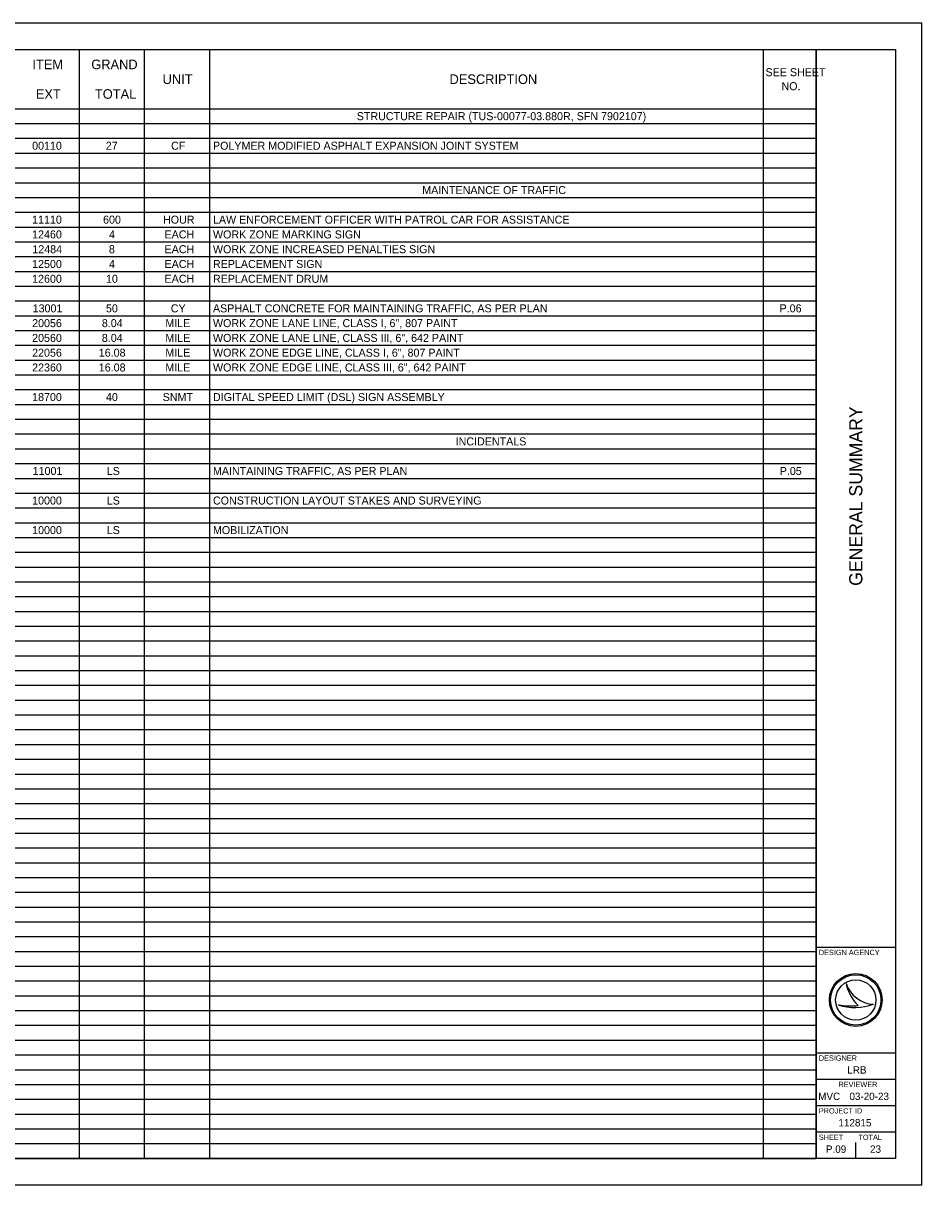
# Model space of a CAD drawing. Extents: x 0 to 924, y -62 to 22.
# Drawn here: x 16.98 to 34, y 0 to 22 of the extents above; entities that cross this region are included whole.
import ezdxf

# ---------------------------------------------------------------- set-up
doc = ezdxf.new("R2010")
doc.units = 0
for name, color, linetype in [('SH_Border', 7, 'Continuous'), ('SH_Cut_Line', 7, 'Continuous'), ('SH_Data', 7, 'Continuous'), ('SH_Text', 7, 'Continuous')]:
    doc.layers.add(name, color=color, linetype=linetype)

msp = doc.modelspace()

# ---------------------------------------------------------------- linework, layer by layer
at = {"layer": 'SH_Border'}
for p, q in [((32, 0.5), (32, 21.5)), ((32, 4.5), (33.5, 4.5)), ((32, 2.5), (33.5, 2.5)), ((32, 2), (33.5, 2)), ((32, 1.5), (33.5, 1.5)), ((32, 1), (33.5, 1))]:
    msp.add_line(p, q, dxfattribs=at)
msp.add_lwpolyline([(1.5, 21.5), (33.5, 21.5), (33.5, 0.5), (1.5, 0.5)], close=True, dxfattribs=at)
at = {"layer": 'SH_Cut_Line'}
msp.add_lwpolyline([(0, 0), (34, 0), (34, 22), (0, 22)], close=True, dxfattribs=at)
at = {"layer": 'SH_Data'}
for p, q in [((32.567, 3.81), (32.567, 3.81)), ((32.417, 3.41), (32.417, 3.41)), ((32.75, 3.5), (32.75, 3.5)), ((33.087, 3.419), (33.087, 3.419)), ((32.375, 0.675), (32.375, 0.675)), ((32.75, 0.5), (32.75, 0.8))]:
    msp.add_line(p, q, dxfattribs=at)
for radius in [0.5, 0.477, 0.477, 0.382]:
    msp.add_circle((32.75, 3.5), radius, dxfattribs=at)
for centre, radius, start, end in [((33.116, 3.998), 0.58, 198.9257, 198.9319), ((33.347, 3.97), 0.796, 191.6379, 191.6421), ((33.116, 3.998), 0.58, 198.9319, 267.1657), ((33.347, 3.97), 0.796, 191.6421, 226.0947), ((32.739, 4.37), 1.013, 251.4576, 290.0832), ((32.648, 4.654), 1.266, 259.4964, 259.4995), ((32.739, 4.37), 1.013, 251.4527, 251.4576), ((32.648, 4.654), 1.266, 259.4995, 276.6672)]:
    msp.add_arc(centre, radius, start, end, dxfattribs=at)
at = {"layer": 'SH_Text'}
for p, q in [((1.5, 21.5), (32, 21.5)), ((18.035, 21.5), (18.035, 0.5)), ((19.27, 21.5), (19.27, 0.5)), ((20.505, 21.5), (20.505, 0.5)), ((30.995, 21.5), (30.995, 0.5)), ((32, 21.5), (32, 0.5)), ((1.5, 20.38), (32, 20.38)), ((1.5, 20.1), (32, 20.1)), ((1.5, 19.82), (32, 19.82)), ((1.5, 19.54), (32, 19.54)), ((1.5, 19.26), (32, 19.26)), ((1.5, 18.98), (32, 18.98)), ((1.5, 18.7), (32, 18.7)), ((1.5, 18.42), (32, 18.42)), ((1.5, 18.14), (32, 18.14)), ((1.5, 17.86), (32, 17.86)), ((1.5, 17.58), (32, 17.58)), ((1.5, 17.3), (32, 17.3)), ((1.5, 17.02), (32, 17.02)), ((1.5, 16.74), (32, 16.74)), ((1.5, 16.46), (32, 16.46)), ((1.5, 16.18), (32, 16.18)), ((1.5, 15.9), (32, 15.9)), ((1.5, 15.62), (32, 15.62)), ((1.5, 15.34), (32, 15.34)), ((1.5, 15.06), (32, 15.06)), ((1.5, 14.78), (32, 14.78)), ((1.5, 14.5), (32, 14.5)), ((1.5, 14.22), (32, 14.22)), ((1.5, 13.94), (32, 13.94)), ((1.5, 13.66), (32, 13.66)), ((1.5, 13.38), (32, 13.38)), ((1.5, 13.1), (32, 13.1)), ((1.5, 12.82), (32, 12.82)), ((1.5, 12.54), (32, 12.54)), ((1.5, 12.26), (32, 12.26)), ((1.5, 11.98), (32, 11.98)), ((1.5, 11.7), (32, 11.7)), ((1.5, 11.42), (32, 11.42)), ((1.5, 11.14), (32, 11.14)), ((1.5, 10.86), (32, 10.86)), ((1.5, 10.58), (32, 10.58)), ((1.5, 10.3), (32, 10.3)), ((1.5, 10.02), (32, 10.02)), ((1.5, 9.74), (32, 9.74)), ((1.5, 9.46), (32, 9.46)), ((1.5, 9.18), (32, 9.18)), ((1.5, 8.9), (32, 8.9)), ((1.5, 8.62), (32, 8.62)), ((1.5, 8.34), (32, 8.34)), ((1.5, 8.06), (32, 8.06)), ((1.5, 7.78), (32, 7.78)), ((1.5, 7.5), (32, 7.5)), ((1.5, 7.22), (32, 7.22)), ((1.5, 6.94), (32, 6.94)), ((1.5, 6.66), (32, 6.66)), ((1.5, 6.38), (32, 6.38)), ((1.5, 6.1), (32, 6.1)), ((1.5, 5.82), (32, 5.82)), ((1.5, 5.54), (32, 5.54)), ((1.5, 5.26), (32, 5.26)), ((1.5, 4.98), (32, 4.98)), ((1.5, 4.7), (32, 4.7)), ((1.5, 4.42), (32, 4.42)), ((1.5, 4.14), (32, 4.14)), ((1.5, 3.86), (32, 3.86)), ((1.5, 3.58), (32, 3.58)), ((1.5, 3.3), (32, 3.3)), ((1.5, 3.02), (32, 3.02)), ((1.5, 2.74), (32, 2.74)), ((1.5, 2.46), (32, 2.46)), ((1.5, 2.18), (32, 2.18)), ((1.5, 1.9), (32, 1.9)), ((1.5, 1.62), (32, 1.62)), ((1.5, 1.34), (32, 1.34)), ((1.5, 1.06), (32, 1.06)), ((1.5, 0.78), (32, 0.78)), ((1.5, 0.5), (32, 0.5))]:
    msp.add_line(p, q, dxfattribs=at)

# ---------------------------------------------------------------- texts
at = {"layer": 'SH_Data'}
msp.add_text('GENERAL SUMMARY', height=0.25, rotation=90, dxfattribs=at).set_placement((32.875, 11.344))
for s, height, p in [('DESIGN AGENCY', 0.1, (32.05, 4.35)), ('DESIGNER', 0.1, (32.05, 2.35)), ('LRB', 0.14, (32.589, 2.105)), ('REVIEWER', 0.1, (32.422, 1.85)), ('MVC', 0.14, (32.038, 1.605)), ('03-20-23', 0.14, (32.629, 1.605)), ('PROJECT ID', 0.1, (32.05, 1.35)), ('112815', 0.14, (32.421, 1.105)), ('SHEET', 0.1, (32.05, 0.85)), ('TOTAL', 0.1, (32.8, 0.85)), ('P.09', 0.14, (32.184, 0.605)), ('23', 0.14, (33.02, 0.605))]:
    msp.add_text(s, height=height, dxfattribs=at).set_placement(p)
at = {"layer": 'SH_Text'}
for s, height, p in [('ITEM', 0.1818, (17.15, 21.129)), ('GRAND', 0.1818, (18.266, 21.129)), ('SEE SHEET ', 0.1515, (31.04, 20.997)), ('UNIT', 0.1818, (19.617, 20.849)), ('DESCRIPTION', 0.18184, (25.053, 20.849)), ('EXT', 0.1818, (17.215, 20.569)), ('TOTAL', 0.1818, (18.335, 20.569)), ('NO.', 0.1515, (31.342, 20.732)), ('STRUCTURE REPAIR (TUS-00077-03.880R, SFN 7902107)', 0.15153, (23.295, 20.164)), ('00110', 0.1515, (17.145, 19.604)), ('27', 0.1515, (18.54, 19.604)), ('CF', 0.1515, (19.778, 19.604)), ('POLYMER MODIFIED ASPHALT EXPANSION JOINT SYSTEM', 0.15153, (20.571, 19.604)), ('MAINTENANCE OF TRAFFIC', 0.15153, (24.536, 18.764)), ('11110', 0.1515, (17.145, 18.204)), ('600', 0.1515, (18.489, 18.204)), ('HOUR', 0.1515, (19.625, 18.204)), ('LAW ENFORCEMENT OFFICER WITH PATROL CAR FOR ASSISTANCE', 0.15153, (20.571, 18.204)), ('12460', 0.1515, (17.145, 17.924)), ('4', 0.152, (18.602, 17.924)), ('EACH', 0.1515, (19.654, 17.924)), ('WORK ZONE MARKING SIGN', 0.15153, (20.571, 17.924)), ('12484', 0.1515, (17.149, 17.644)), ('8', 0.152, (18.599, 17.644)), ('EACH', 0.1515, (19.654, 17.644)), ('WORK ZONE INCREASED PENALTIES SIGN', 0.15153, (20.571, 17.644)), ('12500', 0.1515, (17.145, 17.364)), ('4', 0.152, (18.602, 17.364)), ('EACH', 0.1515, (19.654, 17.364)), ('REPLACEMENT SIGN', 0.15153, (20.571, 17.364)), ('12600', 0.1515, (17.145, 17.084)), ('10', 0.1515, (18.544, 17.084)), ('EACH', 0.1515, (19.654, 17.084)), ('REPLACEMENT DRUM', 0.15153, (20.571, 17.084)), ('13001', 0.1515, (17.155, 16.524)), ('50', 0.1515, (18.544, 16.524)), ('CY', 0.1515, (19.772, 16.524)), ('ASPHALT CONCRETE FOR MAINTAINING TRAFFIC, AS PER PLAN', 0.15153, (20.571, 16.524)), ('P.06', 0.1515, (31.306, 16.524)), ('20056', 0.1515, (17.145, 16.244)), ('8.04', 0.1515, (18.466, 16.244)), ('MILE', 0.1515, (19.669, 16.244)), ('WORK ZONE LANE LINE, CLASS I, 6", 807 PAINT', 0.15153, (20.571, 16.244)), ('20560', 0.1515, (17.145, 15.964)), ('8.04', 0.1515, (18.466, 15.964)), ('MILE', 0.1515, (19.669, 15.964)), ('WORK ZONE LANE LINE, CLASS III, 6", 642 PAINT', 0.15153, (20.571, 15.964)), ('22056', 0.1515, (17.145, 15.684)), ('16.08', 0.1515, (18.408, 15.684)), ('MILE', 0.1515, (19.669, 15.684)), ('WORK ZONE EDGE LINE, CLASS I, 6", 807 PAINT', 0.15153, (20.571, 15.684)), ('22360', 0.1515, (17.145, 15.404)), ('16.08', 0.1515, (18.408, 15.404)), ('MILE', 0.1515, (19.669, 15.404)), ('WORK ZONE EDGE LINE, CLASS III, 6", 642 PAINT', 0.15153, (20.571, 15.404)), ('18700', 0.1515, (17.145, 14.844)), ('40', 0.1515, (18.544, 14.844)), ('SNMT', 0.1515, (19.618, 14.844)), ('DIGITAL SPEED LIMIT (DSL) SIGN ASSEMBLY', 0.15153, (20.571, 14.844)), ('INCIDENTALS', 0.15153, (25.169, 14.004)), ('11001', 0.1515, (17.155, 13.444)), ('LS', 0.1515, (18.559, 13.444)), ('MAINTAINING TRAFFIC, AS PER PLAN', 0.15153, (20.571, 13.444)), ('P.05', 0.1515, (31.309, 13.444)), ('10000', 0.1515, (17.145, 12.884)), ('LS', 0.1515, (18.559, 12.884)), ('CONSTRUCTION LAYOUT STAKES AND SURVEYING', 0.15153, (20.571, 12.884)), ('10000', 0.1515, (17.145, 12.324)), ('LS', 0.1515, (18.559, 12.324)), ('MOBILIZATION', 0.15153, (20.571, 12.324))]:
    msp.add_text(s, height=height, dxfattribs=at).set_placement(p)

doc.saveas('drawing.dxf')
